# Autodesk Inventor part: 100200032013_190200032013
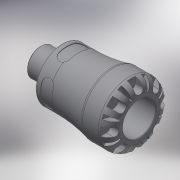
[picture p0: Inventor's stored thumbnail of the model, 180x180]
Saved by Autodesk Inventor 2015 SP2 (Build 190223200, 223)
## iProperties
Created: 2016-12
Part Number: 100200032013_190200032013
Material: Generic
Description: PLASSON MALE ADAPTOR 32X1.1/4" SERIES 1
Document SubType Name: Modeling
Designer: KIM
Mass: 447.839 g
Surface Area: 722.341 cm^2
Volume: 447.839 cm^3
Density: 1 g/cm^3
Appearance: Default
Author: KIM
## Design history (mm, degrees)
derived "1002.ipt"
feature "Solid1::1002.ipt"
tag "TaggingFeature1"
body "Solid1"
other parameters: "d0" = 86, "d1" = 23.1, "d2" = 32, "d4" = 58, "d6" = 55, "d8" = 49.3, "d13" = 7.2, "d14" = 7.2, "d15" = 0, "d17" = 360 deg, "d19" = 8 deg, "d20" = 0.64, "d21" = 0.64, "d22" = 8 deg, "d24" = 0, "d26" = 360 deg, "d32" = 0.925, "d33" = 5.8, "d34" = 41.91, "d35" = 4, "d38" = 21, "d39" = 1.2573, "d42" = 11.2, "d43" = 7.36, "d45" = 14.112, "d46" = 0, "d59" = 360 deg, "d61" = 9.52, "d62" = 0.64, "d64" = 0, "d65" = 0.58, "d_" = 32, "E_" = 58, "H_" = 86, "l_" = 55, "R_" = 41.91, "l_2" = 21, "d9" = 9, "d11" = 58
